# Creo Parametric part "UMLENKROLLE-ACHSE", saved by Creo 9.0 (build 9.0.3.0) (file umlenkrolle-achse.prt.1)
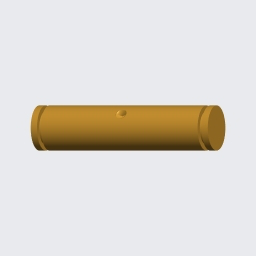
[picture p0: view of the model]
Units: millimeter Kilogram Sec (mmKs); MM, KILOGRAM, SECS
Materials in the file: STAHL

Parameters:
  WERKSTOFF = "Stahl"
  ERSTELLER = "ARINDA"
  BENENNUNG = "XXX"
  TEILETYP = "K"
  PTC_MASTER_MATERIAL = "STAHL"

Other parameters: MASSE

Created from: ARINDA_STARTTEIL.PRT

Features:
  1. coordinate system
  2. datum plane "RECHTS_Y-Z"
  3. datum plane "OBEN_X-Z"
  4. datum plane "VORNE_X-Y"
  5. datum axis
  6. datum axis
  7. datum axis
  8. datum point "PNT0"
  9. revolve "Drehen 1"
  10. hole "Bohrung 1"

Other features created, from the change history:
  coordinate system "CS1"

Other named items: A_X, A_Y, A_Z, CS0

Layers: 01_ACHSEN_STD, 01_EBENEN_STD, 01_KOORDSYS_STD, 01_PUNKTE_STD, VOLUMENGEOMETRIE

Surfaces: 11 cylinder, 6 plane, 2 cone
